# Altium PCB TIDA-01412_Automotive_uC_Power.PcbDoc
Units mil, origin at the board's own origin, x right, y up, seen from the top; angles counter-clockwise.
Board outline 2660 x 1720 mil, 2 copper layers (Top Layer, Bottom Layer), stack 40 mil thick; 78 components, 39 nets, 224 pads, 90 vias.
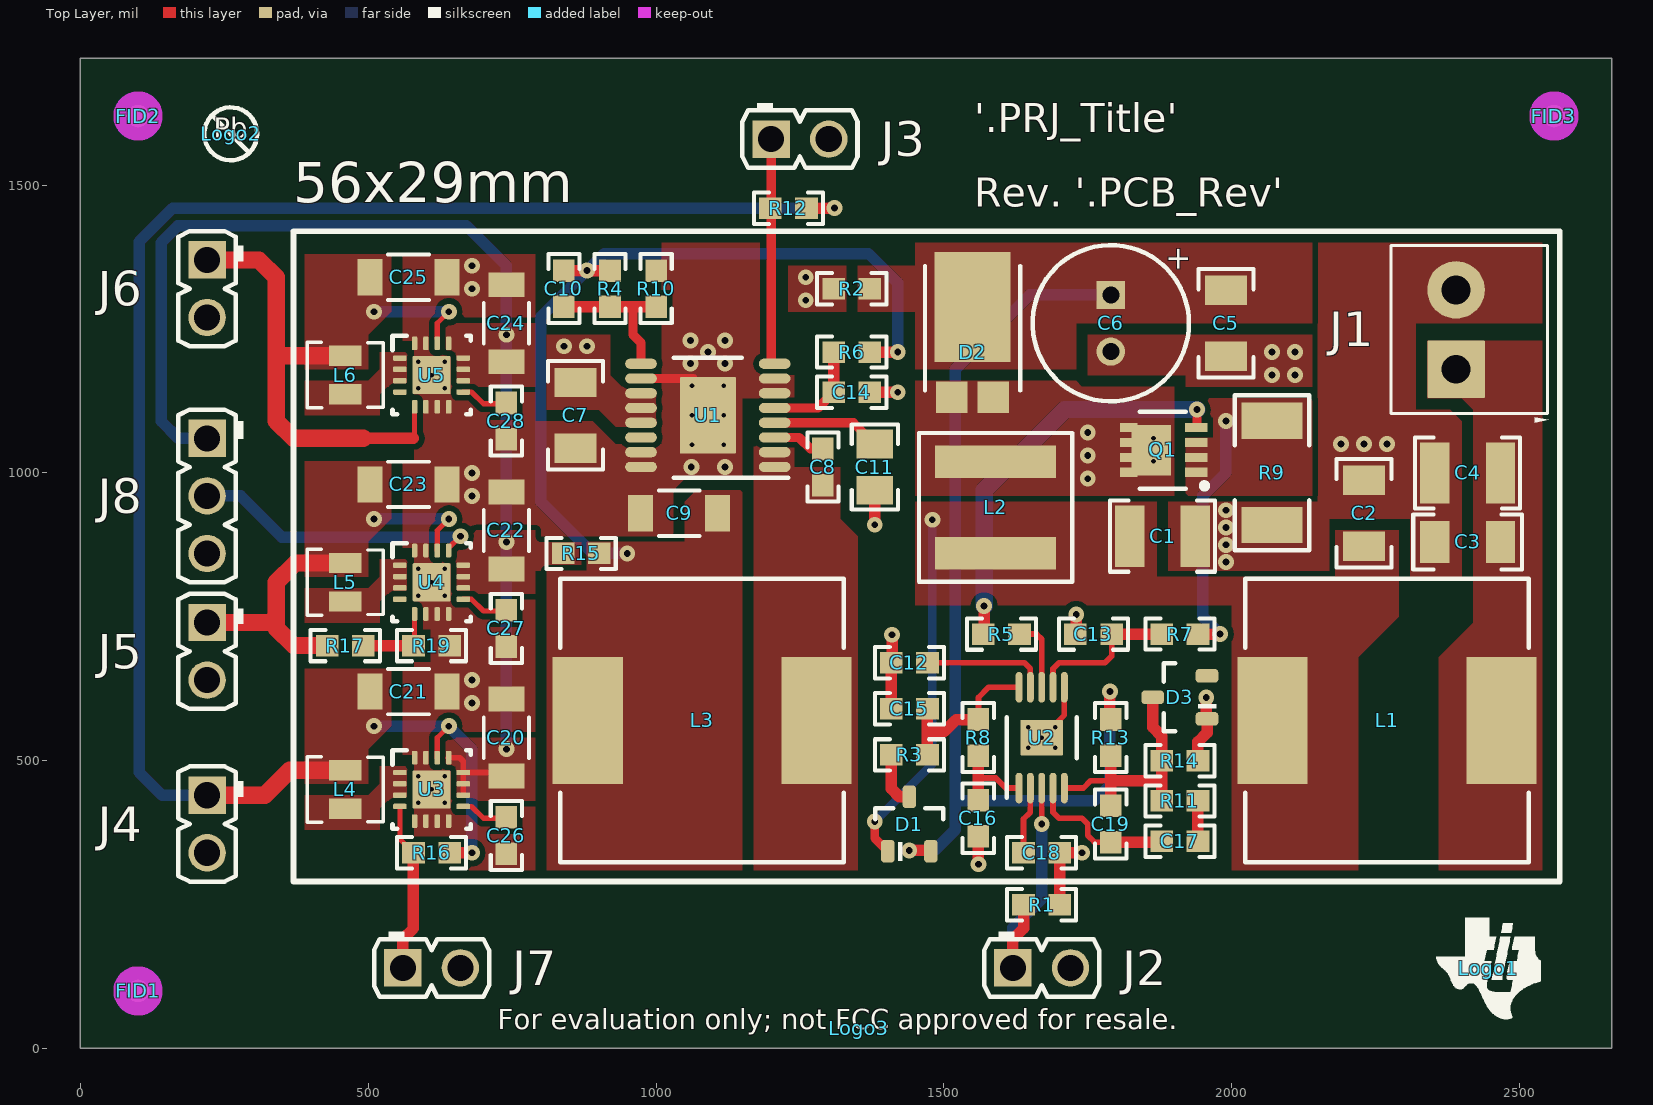
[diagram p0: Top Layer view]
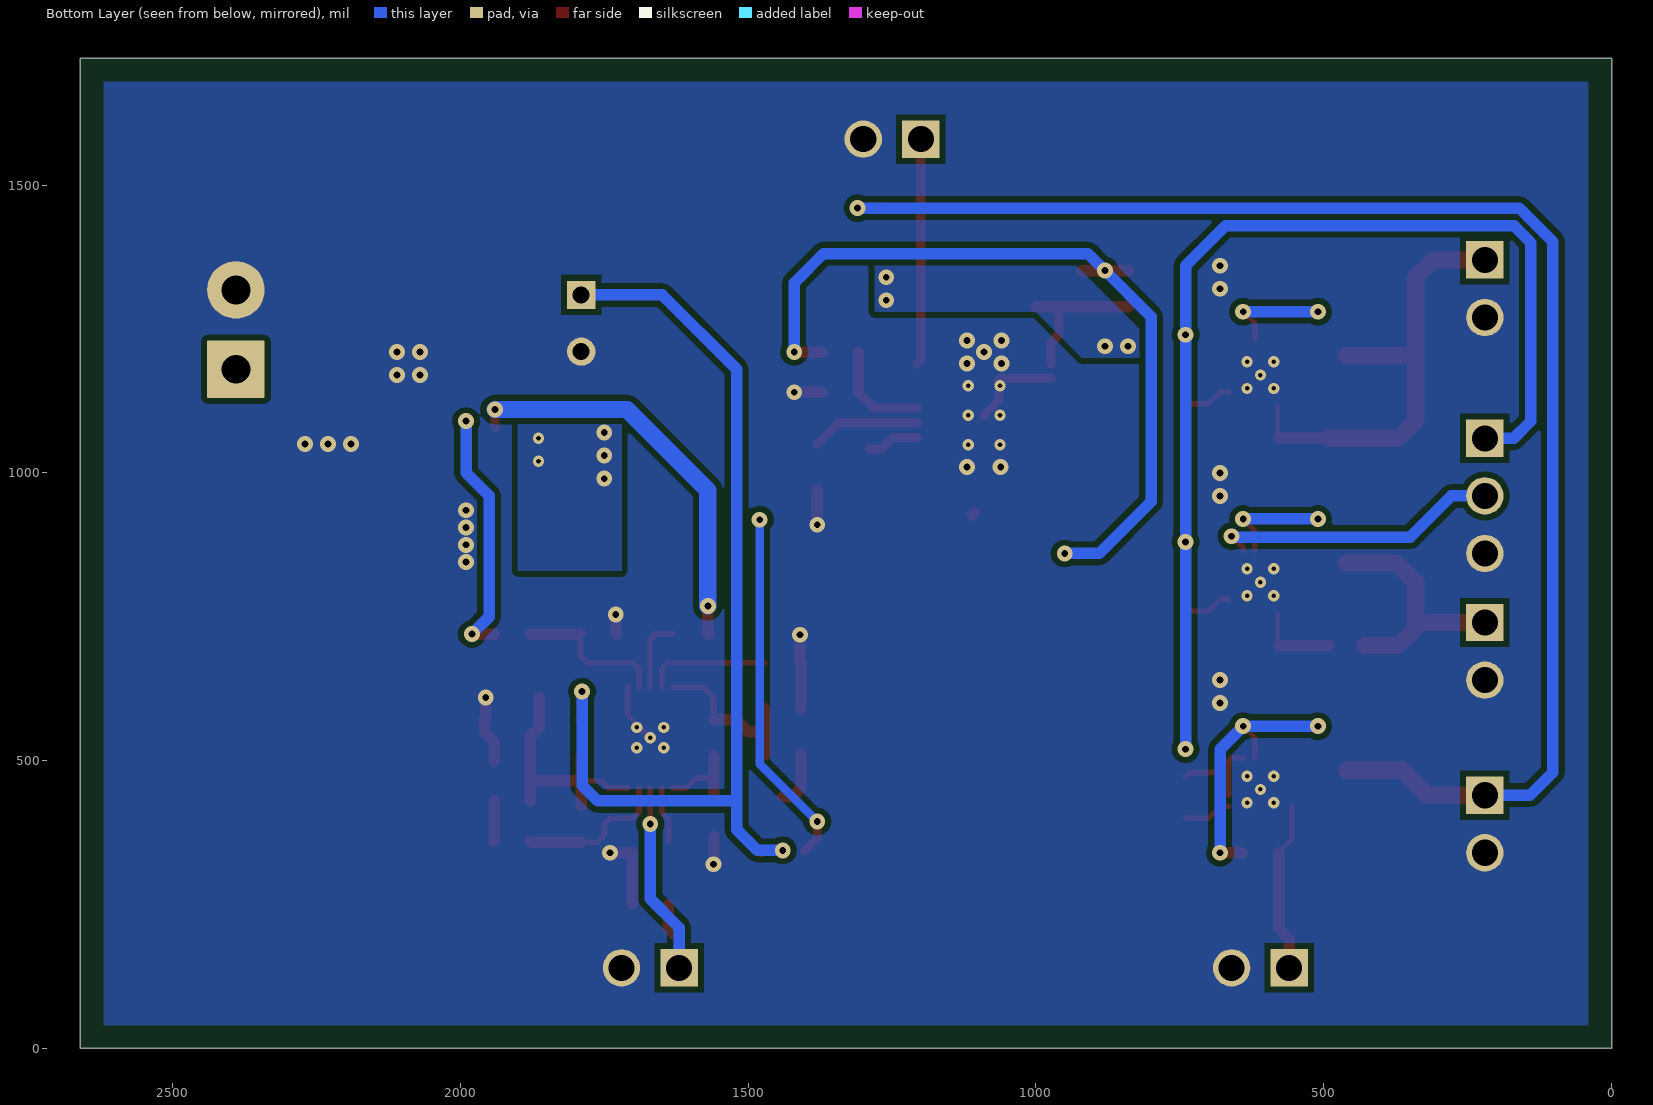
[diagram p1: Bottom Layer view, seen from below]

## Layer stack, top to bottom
Top Solder: solder mask 0.4, Solder Resist, Dk 3.5
Top Layer: signal copper 1.4
Dielectric1: core 37.2, FR-4, Dk 4.8
Bottom Layer: signal copper 1.4
Bottom Solder: solder mask 0.4, Solder Resist, Dk 3.5

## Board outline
0,0 2660,0 2660,1720 0,1720

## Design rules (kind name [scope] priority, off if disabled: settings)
AcuteAngle [All] p1: minimum=4.50000000000000E+0001 checktracksonly=FALSE
AssemblyTestPointUsage [All] p1: valid=2
BoardOutlineClearance BoardOutlineClearance_MountingHoles [OnCopper and InComponentClass('Mounting Holes')] p1: gap=40
BoardOutlineClearance BoardOutlineClearance_Poly [OnCopper and IsPoly] p2: gap=25
BoardOutlineClearance [OnCopper and Not InComponentClass('Logo') and not InComponentClass('FiducialMark') and not InRegion(1000,500,4000,800) and not InPoly] p3: gap=40
Clearance Clearance_Keepouts [((IsTrack Or IsArc) And Not InPoly) And IsFree and IsKeepOut vs ((IsTrack Or IsArc) And Not InPoly) And IsFree and IsKeepOut] p1: gap=0
Clearance Clearance_Poly [InPolygon] p2: gap=10
Clearance [All] p3: gap=7.87
ComponentClearance ComponentClearance_MountingHoles_FiducialMarks [InComponentClass('Mounting Holes') vs InComponentClass('FiducialMark')] p1: gap=50 collisioncheckmode=3 verticalgap=10 showdistances=FALSE
ComponentClearance ComponentClearance_Shunt [InComponentClass('Header') vs InComponentClass('Shunt')] p2: gap=0 collisioncheckmode=3 verticalgap=0 showdistances=FALSE
ComponentClearance ComponentClearance_Logo [InComponentClass('Logo')] p3: gap=50 collisioncheckmode=3 verticalgap=10 showdistances=FALSE
ComponentClearance ComponentClearance_ScrewToNut [(HasFootprint('NY PMS 440 0025 PH')) vs (HasFootprint('Keystone_1902C'))] p4: gap=5 collisioncheckmode=3 verticalgap=10 showdistances=FALSE
ComponentClearance ComponentClearance_MountingHoles [InComponentClass('Mounting Holes')] p5: gap=250 collisioncheckmode=3 verticalgap=100000 showdistances=FALSE
ComponentClearance ComponentClearance_SmallPassives [HasFootprint('0201*') or HasFootprint('0402*') or HasFootprint('0508') or HasFootprint('0603*') or HasFootprint('0612') or HasFootprint('0805*') or HasFootprint('0815*') or HasFootprint('0830*') or HasFootprint('1206*') or HasFootprint('1210*') or HasFootprint('1808*') or HasFootprint('1812*') or HasFootprint('1825*') or HasFootprint('2010*') or HasFootprint('2220*') or HasFootprint('2225*') or HasFootprint('2512*') or HasFootprint('2728*') or HasFootprint('3518*') vs HasFootprint('0201*') or HasFootprint('0402*') or HasFootprint('0508') or HasFootprint('0603*') or HasFootprint('0612') or HasFootprint('0805*') or HasFootprint('0815*') or HasFootprint('0830*') or HasFootprint('1206*') or HasFootprint('1210*') or HasFootprint('1808*') or HasFootprint('1812*') or HasFootprint('1825*') or HasFootprint('2010*') or HasFootprint('2220*') or HasFootprint('2225*') or HasFootprint('2512*') or HasFootprint('2728*') or HasFootprint('3518*')] p6: gap=14.96 collisioncheckmode=3 verticalgap=10 showdistances=FALSE
ComponentClearance ComponentClearance_THtoSMT [IsThruComponent vs IsSMTComponent] p7: gap=25 collisioncheckmode=3 verticalgap=30 showdistances=FALSE
ComponentClearance ComponentClearance_THtoTH [IsThruComponent vs IsThruComponent] p8: gap=20 collisioncheckmode=3 verticalgap=30 showdistances=FALSE
ComponentClearance [All] p9: gap=20 collisioncheckmode=3 verticalgap=10 showdistances=FALSE
DiffPairsRouting [All] p1: maxlimit=100 minlimit=10 mostfreqgap=10 toplayer_minwidth=15 toplayer_maxwidth=15 toplayer_prefwidth=15 bottomlayer_minwidth=15 bottomlayer_maxwidth=15 bottomlayer_prefwidth=15 maxuncoupledlength=1000
FabricationTestPointUsage TestPointUsage [All] p1: valid=2 allowmultiple=FALSE
FabricationTestpoint Testpoint [All] p1: side=3 testpointundercomponent=TRUE minsize=40 maxsize=100 preferedsize=60 minholesize=0 maxholesize=40 preferedholesize=32 testpointgrid=1 allowsidetop=TRUE allowsidebottom=TRUE usegrid=TRUE gridtolerance=0.01
FanoutControl Fanout_LCC [IsLCC] p1: bgadir=Out bgaviamode=Centered fanoutstyle=Auto fanoutdirection=Alternating viagrid=1 // Fanout_LCC (Default Rule)
FanoutControl Fanout_BGA [IsBGA] p2: bgadir=Out bgaviamode=Centered fanoutstyle=Auto fanoutdirection=Alternating viagrid=1 // Fanout_BGA (Default Rule)
FanoutControl Fanout_Default [All] p4: bgadir=Out bgaviamode=Centered fanoutstyle=Auto fanoutdirection=Alternating viagrid=1 // Fanout_Default (Default Rule)
FanoutControl Fanout_Small [(CompPinCount < 5)] p5: bgadir=Out bgaviamode=Centered fanoutstyle=Auto fanoutdirection=OutThenIn viagrid=1 // Fanout_Small (Default Rule)
HoleSize [All] p1: absolutevalues=TRUE maxlimit=251 minlimit=7.87 maxpercent=80.000 minpercent=20.000
MinimumAnnularRing MinimumAnnularRing_ThermalPadVias [IsVia and InAnyComponent] p1: minimumring=5.91
MinimumAnnularRing [All] p2: minimumring=7.87
MinimumSolderMaskSliver MinimumSolderMaskSliver_Logo [InComponentClass('Logo') vs InComponentClass('Logo')] p1: minsoldermaskwidth=0.7
MinimumSolderMaskSliver [All] p2: minsoldermaskwidth=3.94
PlaneConnect [All] p1: planeconnectstyle=Direct reliefexpansion=10 reliefentries=4 reliefconductorwidth=10 reliefairgap=10
PolygonConnect [All] p1: connectstyle=Direct reliefconductorwidth=10 reliefentries=4 polygonreliefangle="90 Angle" airgapwidth=10
RoutingVias ThermalPadVias [IsVia and InAnyComponent] p1: holewidth=7.87 width=19.68 viastyle="Through Hole" minholewidth=7.87 minwidth=19.68 maxholewidth=12.99 maxwidth=23.62
RoutingVias [All] p2: holewidth=16 width=34 viastyle="Through Hole" minholewidth=7.87 minwidth=26 maxholewidth=40 maxwidth=65
SilkToBoardRegionClearance [Not ((IsComment or IsDesignator) And (Hide <> 'False')) and not InRegion(1000,500,4000,800)] p1:
SilkToSilkClearance SilkToSilkClearance_Pb-FreeLogo [(HasFootprint('Pb-Free_Overlay_Medium') OR HasFootprint('Pb-Free_Overlay_Small')) vs (HasFootprint('Pb-Free_Overlay_Medium') OR HasFootprint('Pb-Free_Overlay_Small'))] p1: silktosilkclearance=0
SilkToSilkClearance [All] p2: silktosilkclearance=4
SilkToSolderMaskClearance [(IsPad or IsFill or IsRegion) and InComponent('D3')] p1: minsilkscreentomaskgap=3.9 clearancetoexposedcopper=TRUE
SilkToSolderMaskClearance SilkToComponentPadClearance [(IsPad or IsFill or IsRegion) and InAnycomponent] p2: minsilkscreentomaskgap=5 clearancetoexposedcopper=TRUE
SilkToSolderMaskClearance "Silk to Solder Mask Opening" [All] p3: minsilkscreentomaskgap=4 clearancetoexposedcopper=FALSE
SolderMaskExpansion [All] p1: expansion=1.97
Width [All] p1: maxlimit=100 minlimit=6 preferedwidth=10 checkconnectedcopper=TRUE
15 further rules are at their usual default settings.

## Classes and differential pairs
component class AssemblyNote: ZZ2 ZZ3 ZZ4
component class FiducialMark: FID1 FID2 FID3
component class TIDA-01412_Automotive_uC_Power_Hardware: FID1 FID2 FID3 Logo1 Logo2 Logo3 ZZ2 ZZ3 ZZ4
component class Logo: Logo1
component class Header: J2 J3 J4 J5 J6 J7 J8
component class TIDA-01412_Automotive_uC_Power: C1 C2 C3 C4 C5 C6 C7 C8 C9 C10 C11 C12 C13 C14 C15 C16 C17 C18 C19 C20 C21 C22 C23 C24 C25 C26 C27 C28 D1 D2 D3 J1 J2 J3 J4 J5 J6 J7 J8 L1 L2 L3 L4 L5 L6 Q1 R1 R2 R3 R4 R5 R6 R7 R8 R9 R10 R11 R12 R13 R14 R15 R16 R17 R19 U1 U2 U3 U4 U5

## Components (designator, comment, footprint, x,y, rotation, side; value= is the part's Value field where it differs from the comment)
C1 "GRM32ER71H475KA88L" 1210_270 1880,890 r0 top
C2 "GRM31MR71H105KA88L" 1206 2230,930 r90 top
C3 "GRM31MR71H105KA88L" 1206 2410,880 r180 top
C4 "GRM32ER71H475KA88L" 1210_270 2410,1000 r180 top
C5 "GRM31MR71H105KA88L" 1206 1990,1260 r270 top
C6 "35ZL56MEFCTA6.3X11" ZL_630x1100 1790,1260 r270 top
C7 "GRM31MR71H105KA88L" 1206 860,1100 r270 top
C8 "GRM188R71E474KA12D" 0603 1290,1010 r90 top
C9 "GCM31CR71A226KE02" 1206_180 1040,930 r180 top
C10 "GRM1885C1H101JA01D" 0603 840,1320 r270 top
C11 "GRM21BR71A475KA73L" 0805_HV 1380,1010 r90 top
C12 "GRM188R71C105KA12D" 0603 1440,670 r180 top
C13 "GRM1885C1H101JA01D" 0603 1760,720 r180 top
C14 "GCM188R71H104KA57D" 0603 1340,1140 r0 top
C15 "GCM188R71H104KA57D" 0603 1440,590 r180 top
C16 "GRM188R71H221KA01D" 0603 1560,400 r270 top
C17 "C0603X103K5RACTU" 0603 1910,360 r0 top
C18 "GCM188R71H104KA57D" 0603 1670,340 r0 top
C19 "GRM1885C1H390JA01D" 0603 1790,390 r90 top
C20 "GCM31CR71A226KE02" 1206_180 740,540 r90 top
C21 "GCM31CR71A226KE02" 1206_180 570,620 r0 top
C22 "GCM31CR71A226KE02" 1206_180 740,900 r90 top
C23 "GCM31CR71A226KE02" 1206_180 570,980 r0 top
C24 "GCM31CR71A226KE02" 1206_180 740,1260 r90 top
C25 "GCM31CR71A226KE02" 1206_180 570,1340 r0 top
C26 "GRM188R71H332KA01D" 0603 740,370 r270 top
C27 "GRM188R71H332KA01D" 0603 740,730 r270 top
C28 "GRM188R71H332KA01D" 0603 740,1090 r270 top
D1 "BAS40-05-7-F" SOT-23 1440,390 r90 top
D2 "PDS560-13" PowerDI5 1550,1210 r90 top
D3 "BZX84B8V2LT1G" SOT-23 1910,610 r180 top
FID1 "Fiducial" Fiducial10-20 100,100 r0 top
FID2 "Fiducial" Fiducial10-20 100,1620 r90 top
FID3 "Fiducial" Fiducial10-20 2560,1620 r90 top
J1 "ED555/2DS" TERM_BLK_ED555-2DS 2390,1180 r90 top
J2 "61300211121" WURTH_61300211121 1670,140 r0 top
J3 "61300211121" WURTH_61300211121 1250,1580 r0 top
J4 "61300211121" WURTH_61300211121 220,390 r270 top
J5 "61300211121" WURTH_61300211121 220,690 r270 top
J6 "61300211121" WURTH_61300211121 220,1320 r270 top
J7 "61300211121" WURTH_61300211121 610,140 r0 top
J8 "61300311121" WURTH_61300311121 220,960 r270 top
L1 "B82464–G4472–M" B82477P4 2270,570 r0 top
L2 "XAL6060-822MEB" XAL6060 1590,940 r90 top
L3 "B82464–G4222–M" B82477P4 1080,570 r180 top
L4 "VLF302510MT-2R2M" VLF302510MT 460,450 r90 top
L5 "VLF302510MT-2R2M" VLF302510MT 460,810 r90 top
L6 "VLF302510MT-2R2M" VLF302510MT 460,1170 r90 top
Logo1 "Texas Instruments" TI_Symbol_Overlay_Small 2446,139 r0 top
Logo2 "Pb-Free Symbol" Pb-Free_Overlay_Small 261,1589 r0 top
Logo3 "FCC disclaimer" FCC_disclaimer 1352,35 r0 top
Q1 "SiSA04DN-T1-GE3" PowerPAK_1212-8 1880,1040 r180 top
R1 "CRCW060310K0FKEA" 0603 1670,250 r180 top
R2 "CRCW06030000Z0EA" 0603 1340,1320 r180 top
R3 "CRCW060310R0FKEA" 0603 1440,510 r0 top
R4 "CRCW060382K5FKEA" 0603 920,1320 r90 top
R5 "CRCW06030000Z0EA" 0603 1600,720 r180 top
R6 "CRCW06033R01FKEA" 0603 1340,1210 r0 top
R7 "CRCW06031K00FKEA" 0603 1910,720 r0 top
R8 "CRCW0603221KFKEA" 0603 1560,540 r90 top
R9 "WSL2010R0200FEA18" 2010 2070,1000 r90 top
R10 "CRCW060316K5FKEA" 0603 1000,1320 r270 top
R11 "CRCW060333K2FKEA" 0603 1910,430 r0 top
R12 "CRCW060310K0FKEA" 0603 1230,1460 r0 top
R13 "CRCW0603200KFKEA" 0603 1790,540 r90 top
R14 "CRCW060316K9FKEA" 0603 1910,500 r180 top
R15 "CRCW06030000Z0EA" 0603 870,860 r0 top
R16 "CRCW060310K0FKEA" 0603 610,340 r0 top
R17 "CRCW060373K2FKEA" 0603 460,700 r180 top
R19 "CRCW060323K2FKEA" 0603 610,700 r180 top
U1 "LM53603AQPWPRQ1" PWP0016H_N 1090,1100 r180 top
U2 "TPS40210QDGQRQ1" DGQ0010D_N 1670,540 r90 top
U3 "TPS62133AQRGTRQ1" RGT0016C 610,450 r0 top
U4 "TPS62130AQRGTRQ1" RGT0016C 610,810 r0 top
U5 "TPS6213013AQRGTRQ1" RGT0016C 610,1170 r0 top
ZZ2 "These assemblies are ESD sensitive, ESD precautions shall be observed." AssemblyNote 13,2036.11 r0 top
ZZ3 "These assemblies must be clean and free from flux and all contaminants. Use of no clean flux is not acceptable." AssemblyNote 13,1947.56 r0 top
ZZ4 "These assemblies must comply with workmanship standards IPC-A-610 Class 2, unless otherwise specified." AssemblyNote 13,1859 r0 top

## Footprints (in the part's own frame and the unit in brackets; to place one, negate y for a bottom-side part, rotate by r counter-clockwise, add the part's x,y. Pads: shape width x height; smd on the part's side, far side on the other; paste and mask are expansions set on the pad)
0603 [mm] "0603 from SM-752 data"
  rect 1x0.95 smd: 1(-0.8,0) 2(0.8,0)
  silkscreen extent -1.52,-0.69 1.52,0.69, body extent -0.87,-0.47 0.87,0.47, height 1
0805_HV [mil] "0805 with 30mil clearance between pads"
  rect 50x63 smd: 1(-40,0) 2(40,0)
  silkscreen extent -74,-40 74,40, body extent -43,-29 43,29, height 57
1206 [mm] "1206 from SM-752 data"
  rect 1.3x1.85 smd: 1(-1.45,0) 2(1.45,0)
  silkscreen extent -2.4,-1.21 2.4,1.21, body extent -1.7,-0.9 1.7,0.9, height 1.35
1206_180 [mm] "1206_180"
  rect 1.1x1.6 smd: 1(-1.7,0) 2(1.7,0)
  silkscreen extent -0.9,-1 0.9,1, body extent -1.75,-0.95 1.75,0.95, height 1.8
1210_270 [mm] "1210"
  rect 1.3x2.7 smd: 1(-1.45,0) 2(1.45,0)
  silkscreen extent -2.32,-1.57 2.32,1.57, body extent -1.7,-1.35 1.7,1.35, height 2.7
2010 [mm] "Chip Capacitor, Body 5.08x2.54mm, IPC Medium Density"
  rect 1.6x2.7 smd: 1(-2.3,0) 2(2.3,0)
  silkscreen extent -3.42,-1.65 3.42,1.65, body extent -2.73,-1.45 2.73,1.45, height 1.66
AssemblyNote [mil] "Assembly Note"
B82477P4 [mm] "SMD, 2-Leads, Body 12.5x12.5mm"
  rect 3.1x5.6 smd: 1(-5.05,0) 2(5.05,0)
  silkscreen extent -6.25,-6.25 6.25,6.25, body extent -6.25,-6.25 6.25,6.25, height 8.5
DGQ0010D_N [mm] "TSSOP, 10-Leads, Body 3x3mm, Pitch 0.5mm, Thermal Pad 1.88x1.57mm, IPC Medium Density"
  rrect100% 1.35x0.3 smd: 1(-2.225,1) 2(-2.225,0.5) 3(-2.225,0) 4(-2.225,-0.5) 5(-2.225,-1) 6(2.225,-1) 7(2.225,-0.5) 8(2.225,0) 9(2.225,0.5) 10(2.225,1)
  rrect6% 1.57x1.88 smd: 11(0,0)
  silkscreen extent -2.65,-1.55 0.9,1.55, body extent -2.46,-1.5 2.46,1.5, height 1.1
FCC_disclaimer [mil]
Fiducial10-20 [mm]
  round 1 smd mask+0.5: 1(0,0)
  Top Layer keep-out circle w1.178: c0,0 r0.5
Pb-Free_Overlay_Small [mil]
  silkscreen extent -46,-46 46,46
PowerDI5 [mm] "Diodes Inc recommended land pattern, ap02001.pdf rev 60"
  rect 1.4x1.39 smd: 1(-1.991,0.92) 2(-1.991,-0.92)
  rect 4.86x3.36 smd: 3(1.991,0)
  silkscreen extent -1.7,-2.1 3.8,2.1, body extent -2.27,-2.03 4.33,2.03, height 1.17
PowerPAK_1212-8 [mil] "Vishay PowerPAK 1212-8, Body 3.4x3.2mm (max), Pitch 0.65mm, IPC Medium Density"
  rect 39x16 smd mask+2.01: 1(-58.75,39) 2(-58.75,13) 3(-58.75,-13) 4(-58.75,-39)
  rect 30x16 smd mask+2.01: 5(58.75,-39) 6(58.75,-13) 7(58.75,13) 8(58.75,39)
  rect 68x88 smd mask+2.01: 9(19.75,0.61)
  silkscreen extent -78,-66 40,68, body extent -65,-65 65,65, height 43
PWP0016H_N [mm] "TSOP, 16-Leads, Body 5x4.4mm, Pitch 0.65mm, Thermal Pad 2.48x3.37 mm, IPC Medium Density"
  rrect100% 1.4x0.45 smd: 1(-2.95,2.275) 2(-2.95,1.625) 3(-2.95,0.975) 4(-2.95,0.325) 5(-2.95,-0.325) 6(-2.95,-0.975) 7(-2.95,-1.625) 8(-2.95,-2.275) 9(2.95,-2.275) 10(2.95,-1.625) 11(2.95,-0.975) 12(2.95,-0.325) 13(2.95,0.325) 14(2.95,0.975) 15(2.95,1.625) 16(2.95,2.275)
  rrect4% 2.48x3.37 smd: 17(0,0)
  silkscreen extent -3.55,-2.55 1.5,2.75, body extent -3.21,-2.5 3.21,2.5, height 1
RGT0016C [mm] "QFN, 16-Leads, Body 3x3mm, Pitch 0.5mm, Thermal Pad 1.7x1.7mm, TI Recommended"
  rrect42% 0.6x0.24 smd: 1(-1.4,0.75) 2(-1.4,0.25) 3(-1.4,-0.25) 4(-1.4,-0.75) 9(1.4,-0.75) 10(1.4,-0.25) 11(1.4,0.25) 12(1.4,0.75)
  rrect42% 0.24x0.6 smd: 5(-0.75,-1.4) 6(-0.25,-1.4) 7(0.25,-1.4) 8(0.75,-1.4) 13(0.75,1.4) 14(0.25,1.4) 15(-0.25,1.4) 16(-0.75,1.4)
  rrect6% 1.55x1.55 on Top Paste: 17(0,0)
  rrect6% 1.68x1.68 smd paste-0.85: 17(0,0)
  silkscreen extent -1.72,-1.73 1.72,1.73, body extent -1.5,-1.5 1.5,1.5, height 1
SOT-23 [mm] "SOT23, 3-Leads, Body 2.9x1.3mm, Pitch 0.95mm, Lead Span 2.5mm, IPC Medium Density"
  rrect50% 1x0.6 smd: 1(-1.2,0.95) 2(-1.2,-0.95) 3(1.2,0)
  silkscreen extent -1.63,-1.5 0.7,1.5, body extent -1.16,-1.45 1.21,1.45, height 1
TERM_BLK_ED555-2DS [mil]
  rrect4% 100x100 hole 50: 1(0,0)
  round 100 hole 50: 2(138,0)
  silkscreen extent -93,-161 215,113, body extent -69,-150 207,106, height 323
TI_Symbol_Overlay_Small [mil]
  silkscreen extent -90,-88 91,88
VLF302510MT [mm] "TDK"
  rect 0.9x1.45 smd: 1(-0.85,0) 2(0.85,0)
  silkscreen extent -1.45,-1.68 1.45,1.68, body extent -1.35,-1.6 1.35,1.6, height 1
WURTH_61300211121 [mm] "Header, 2.54mm, 2x1, TH"
  rect 1.65x1.65 hole 1.15: 1(-1.27,0)
  round 1.65 hole 1.15: 2(1.27,0)
  silkscreen extent -2.54,-1.27 2.54,1.6, body extent -2.54,-1.27 2.54,1.27, height 8.54
WURTH_61300311121 [mm] "Header, 2.54mm, 3x1, TH"
  rect 1.65x1.65 hole 1.15: 1(-2.54,0)
  round 1.65 hole 1.15: 2(0,0) 3(2.54,0)
  silkscreen extent -3.81,-1.27 3.81,1.6, body extent -3.81,-1.27 3.81,1.27, height 8.54
XAL6060 [mil] "Coilcraft recommended land pattern Document 887-4 Revised 11/20/12"
  rect 56x210 smd: 1(-79.5,0) 2(79.5,0)
  silkscreen extent -129,-133 129,133, body extent -129,-133 129,133, height 240
ZL_630x1100 [mm] "RUBYCON"
  rect 1.25x1.25 hole 0.75: 1(-1.25,0)
  round 1.25 hole 0.75: 2(1.25,0)
  silkscreen extent -3.45,-3.45 3.45,3.45, body extent -3.37,-3.39 3.4,3.39, height 12.51

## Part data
C1 C4: "CAP, CERM, 4.7 µF, 50 V, +/- 10%, X7R, 1210"
C2 C3 C5 C7: "CAP, CERM, 1 µF, 50 V, +/- 10%, X7R, 1206"
C6: "CAP, AL, 56 µF, 35 V, +/- 20%, 0.13 ohm, TH"
C8: "CAP, CERM, 0.47 µF, 25 V, +/- 10%, X7R, 0603"
C9 C20 C21 C22 C23 C24 C25: "CAP, CERM, 22 µF, 10 V, +/- 10%, X7R, AEC-Q200 Grade 1, 1206"
C10 C13: "CAP, CERM, 100 pF, 50 V, +/- 5%, C0G/NP0, 0603"
C11: "CAP, CERM, 4.7 µF, 10 V, +/- 10%, X7R, 0805"
C12: "CAP, CERM, 1 µF, 16 V, +/- 10%, X7R, 0603"
C14 C15 C18: "CAP, CERM, 0.1 µF, 50 V, +/- 10%, X7R, 0603"
C16: "CAP, CERM, 220 pF, 50 V, +/- 10%, X7R, 0603"
C17: "CAP, CERM, 0.01 µF, 50 V, +/- 10%, X7R, 0603"
C19: "CAP, CERM, 39 pF, 50 V, +/- 5%, C0G/NP0, 0603"
C26 C27 C28: "CAP, CERM, 3300 pF, 50 V, +/- 10%, X7R, 0603"
D1: "Diode, Schottky, 40 V, 0.2 A, SOT-23"
D2: "Diode, Schottky, 60 V, 5 A, PowerDI5"
D3: "Diode, Zener, 8.2 V, 225 mW, SOT-23"
FID1 FID2 FID3: "Fiducial mark.  There is nothing to buy or mount."
J1: "Terminal Block, 6A, 3.5mm Pitch, 2-Pos, TH"
J2 J3 J4 J5 J6 J7: "Header, 2.54 mm, 2x1, Gold, TH"
J8: "Header, 2.54 mm, 3x1, Gold, TH"
L1: library part B82477P4103M000, "Inductor, Shielded, Ferrite, 4.7 µH, 4.9 A, 0.015 ohm, SMD"
L2: "Inductor, Shielded, Composite, 8.2 µH, 8.4 A, 0.02 ohm, SMD"
L3: library part B82477P4103M000, "Inductor, Shielded, Ferrite, 2.2 µH, 6.5 A, 0.01 ohm, SMD"
L4 L5 L6: "Inductor, Shielded, Ferrite, 2.2 µH, 1.23 A, 0.084 ohm, SMD"
Logo1: library part TI_Logo, "Texas Instrument Corporate Signature"
Logo2: library part Pb-Free
Logo3: library part FCC_disclaimer, "FCC_disclaimer"
Q1: "MOSFET, N-CH, 30 V, 40 A, PowerPAK 1212"
R1 R12 R16: "RES, 10.0 k, 1%, 0.1 W, 0603"
R2 R5 R15: "RES, 0, 5%, 0.1 W, 0603"
R3: "RES, 10.0, 1%, 0.1 W, 0603"
R4: "RES, 82.5 k, 1%, 0.1 W, 0603"
R6: "RES, 3.01, 1%, 0.1 W, 0603"
R7: "RES, 1.00 k, 1%, 0.1 W, 0603"
R8: "RES, 221 k, 1%, 0.1 W, 0603"
R9: "RES, 0.02, 1%, 1 W, 2010"
R10: "RES, 16.5 k, 1%, 0.1 W, 0603"
R11: "RES, 33.2 k, 1%, 0.1 W, 0603"
R13: "RES, 200 k, 1%, 0.1 W, 0603"
R14: "RES, 16.9 k, 1%, 0.1 W, 0603"
R17: "RES, 73.2 k, 1%, 0.1 W, 0603"
R19: "RES, 23.2 k, 1%, 0.1 W, 0603"
U1: "5V/3.3V/ADJ, 3A, Buck Regulator For Automotive Applications, PWP0016H"
U2: "4.5-V TO 52-V INPUT CURRENT MODE BOOST CONTROLLER, DGQ0010D"
U3 U4: "3V to 17-V 3A Step-Down Converter with DCS-Control™, RGT0016C"
U5: "3V-17V 3A Step-Down Converter With DCS-Control, RGT0016C (VQFN-16)"
ZZ2 ZZ3 ZZ4: library part AssemblyNote

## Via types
v1: diameter 27.56, hole 11.81, Top Layer to Bottom Layer, tented both sides, 62 vias
v2: diameter 19.68, hole 7.87, Top Layer to Bottom Layer, 22 vias
v3: diameter 19.68, hole 7.87, Top Layer to Bottom Layer, tented top, 6 vias

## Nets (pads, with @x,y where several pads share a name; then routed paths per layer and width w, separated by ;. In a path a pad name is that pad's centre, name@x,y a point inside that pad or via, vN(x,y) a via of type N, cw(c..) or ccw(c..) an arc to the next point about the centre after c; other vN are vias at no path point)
GND: C1.2 C2.2 C3.2 C4.2 C5.2 C6.2 C7.2 C9.2 C11.1 C12.2 C13.2 C14.2 C15.2 C16.2 C18.2 C20.2 C21.2 C22.2 C23.2 C24.2 C25.2 C26.2 C27.2 C28.2 D3.1 J1.2 J2.2 J3.2 J4.2 J5.2 J6.2 J7.2 J8.3 R1.1 R9.1 R10.1 R14.1 R19.1 U1.6 U1.7 U1.10 U1.15 U1.16 U1.17 U2.6 U2.11 U3.5 U3.6 U3.7 U3.8 U3.15 U3.16 U3.17@610,450 U4.6 U4.7 U4.8 U4.15 U4.16 U4.17@610,810 U5.6 U5.7 U5.8 U5.15 U5.16 U5.17@610,1170 | length 835.4
  Top Layer w10: v2(1670,540) 1709.37,579.37 U2.6
  Top Layer w16: U1.10 1063.98,1163.98 1063.98,1126.02 U1.17
  Top Layer w20: C14.2 v1(1420,1140) ; v1(1380,910) C11.1 ; C15.2 C12.2 1410,671.5 v1(1410,718.7) ; v1(1560,320) C16.2 ; R1.1 C18.2 v1(1740,340) ; C13.2 1730,721.5 v1(1730,754.02) ; R14.1 1941.5,532.6 1957.24,548.35 D3.1 1955.79,574.06 v1(1955.79,610)
  other v1: 680,600 680,640 1990,845 1990,875 1990,905 1990,935 680,960 680,1000 1061.3,1010 1120,1010 2190,1050 2230,1050 2270,1050 2070,1170 2110,1170 1060,1190 1120,1190 1090,1210 2070,1210 2110,1210 1060,1230 1120,1230 680,1320 680,1360
  other v2: 586.77,426.77 633.23,426.77 610,450 586.77,473.23 633.23,473.23 1646.38,522.28 1693.62,522.28 1646.38,557.72 1693.62,557.72 586.77,786.77 633.23,786.77 610,810 586.77,833.23 633.23,833.23 586.77,1146.77 633.23,1146.77 610,1170 586.77,1193.23 633.23,1193.23
  other v3: 1062.44,1048.82 1117.56,1048.82 1062.44,1100 1117.56,1100 1062.44,1151.18 1117.56,1151.18
NetC1_1: C1.1 C2.1 D1.1 L1.1 L2.1 | length 626.7
  Top Layer w15: v1(1380,394.21) 1380,365.35 D1.1
  Bottom Layer w15: v1(1380,394.21) 1480,494.21 v1(1480,918.7)
NetC3_1: C3.1 C4.1 J1.1 L1.2
NetC7_1: C7.1 R2.2 U1.11 U1.12 U1.13
  other v1: 840,1220 880,1220 1260,1300 1260,1340
NetC8_1: C8.1 L3.1 U1.1 U1.2
NetC8_2: C8.2 U1.3 | length 92.2
  Top Layer w16: U1.3 1248.39,1061.61 1268.5,1041.5 C8.2
NetC9_1: C9.1 C10.1 L3.2 R4.2 R6.2 R15.2 | length 1448.1
  Top Layer w20: C10.1 v1(880,1351.5) R4.2 ; C9.1 C9.1@1110,926.93 ; R6.2 v1(1420,1210)
  Bottom Layer w20: v1(950,860) 890,860 800,950 800,1271.5 v1(880,1351.5) 880.47,1351.5 910,1381.02 1368.98,1381.02 1420,1330 v1(1420,1210)
NetC10_2: C10.2 R4.1 R10.2 U1.9 | length 264.7
  Top Layer w16: 960,1288.5 960,1240 973.86,1226.14 U1.9
  Top Layer w20: C10.2 R4.1 960,1288.5 R10.2
NetC11_2: C11.2 U1.4 | length 189.3
  Top Layer w16: U1.4 1342.8,1087.2 C11.2
NetC12_1: C12.1 U2.9 | length 215.2
  Top Layer w10: C12.1 1640,670 1650.31,659.69 U2.9
NetC13_1: C13.1 R7.1 U2.7 | length 268.4
  Top Layer w10: U2.7 1689.68,659.68 1700,670 1780,670 1791.5,681.5 C13.1
  Top Layer w20: C13.1 R7.1
NetC14_1: C14.1 R6.1 U1.5 | length 183.6
  Top Layer w16: U1.5 1281.3,1112.8 C14.1
  Top Layer w20: C14.1 R6.1
NetC15_1: C15.1 R3.2 R8.2 U2.10 | length 293.8
  Top Layer w10: R8.2 1560,610 1577.6,627.6 U2.10
  Top Layer w20: R3.2 1471.5,550 ; C15.1 1471.5,550 ; R8.2 1521.5,571.5 1500,550 1471.5,550
NetC16_1: C16.1 R8.1 U2.1 | length 154.9
  Top Layer w10: 1560,470 1590,470 1607.6,452.4 U2.1
  Top Layer w20: C16.1 1560,470 R8.1
NetC17_1: C17.1 C19.1 U2.4 | length 264.7
  Top Layer w10: U2.4 1689.68,410.32 1700,400 1740,400 1750,390 1750,370 1761.5,358.5 C19.1
  Top Layer w20: C19.1 1877.01,358.5 C17.1
NetC17_2: C17.2 R11.2 | length 70
  Top Layer w20: C17.2 R11.2
NetC18_1: C18.1 U2.2 | length 97.3
  Top Layer w10: 1638.5,360 1638.5,398.5 1650.31,410.31 U2.2
NetC19_2: C19.2 D3.3 R11.1 R13.1 R14.2 U2.5 | length 450
  Top Layer w10: U2.5 1742.4,452.4 1755,465 1790,465
  Top Layer w20: C19.2 1790,465 ; R13.1 1790,465 ; D3.3 1862.76,558.35 1878.5,542.6 R14.2 1878.5,470 ; R11.1 1878.5,470 ; 1790,465 1873.5,465 1878.5,470
NetC20_1: C20.1 C22.1 C24.1 J8.1 R15.1 U3.10 U3.11 U3.12 U3.13 U4.10 U4.11 U4.12 U5.10 U5.11 U5.12 U5.13 | length 2047.8
  Top Layer w10: U3.13 658.88,505.12 665.12,498.88 U3.12 ; U3.10 U3.11 U3.12 ; C20.1 733.54,479.53 U3.12
  Bottom Layer w20: J8.1 170,1060 140,1090 140,1400 169.4,1429.4 670.6,1429.4 740,1360 v1(740,1240) v1(740,520)
  other v1: 740,880
NetC23_1: C23.1 J5.1 L5.2 R17.2 U4.14 | length 632.2
  Top Layer w9: U4.14 619.84,899.84 v1(640,920)
  Top Layer w30: J5.1 330,740 340,750 ; R17.2 370,700 340,730 340,750 ; L5.2 373.46,843.46 340,810 340,750
  Bottom Layer w20: v1(510,920) v1(640,920)
NetC25_1: C25.1 J6.1 L6.2 U5.5 U5.14 | length 996.4
  Top Layer w9: 578.5,1060 580.47,1061.97 U5.5 ; U5.14@619.84,1233.66 619.84,1259.84 v1(640,1280)
  Top Layer w20: 491.5,1060 578.5,1060
  Top Layer w30: J6.1 310,1370 340,1340 340,1210 ; L6.2 346.54,1203.46 340,1210 ; 491.5,1060 370,1060 340,1090 340,1210
  Bottom Layer w20: v1(510,1280) v1(640,1280)
NetC26_1: C26.1 U3.9 | length 84
  Top Layer w9: U3.9 679.53,420.47 700,400 738.5,400 C26.1
NetC27_1: C27.1 U4.9 | length 84
  Top Layer w9: U4.9 679.53,780.47 700,760 738.5,760 C27.1
NetC28_1: C28.1 U5.9 | length 84
  Top Layer w9: U5.9 679.53,1140.47 700,1120 738.5,1120 C28.1
NetD1_3: D1.3 R3.1 | length 95.9
  Top Layer w20: R3.1 1408.5,451.5 1422.76,437.24 D1.3
NetD2_1: D2.1 D2.2 L2.2 Q1.5 Q1.6 Q1.7 Q1.8 Q1.9
  other v1: 1750,990 1750,1030 1750,1070
  other v2: 1864.25,1020 1864.25,1060
NetJ2_1: J2.1 R1.2 U2.3 | length 450.8
  Top Layer w10: v1(1670,390) U2.3
  Top Layer w20: J2.1 1620,190 1638.5,208.5 R1.2
  Bottom Layer w20: J2.1 1620,210 1670,260 v1(1670,390)
NetJ3_1: J3.1 R12.1 U1.8 | length 393
  Top Layer w16: J3.1 1200,1195.71 U1.8
NetJ7_1: J7.1 R16.1 U3.4 | length 297.9
  Top Layer w9: U3.4 554.88,363.62 R16.1
  Top Layer w20: J7.1 560,190 578.5,208.5 R16.1
NetJ8_2: J8.2 U4.13 | length 503.7
  Top Layer w9: U4.13 639.53,869.53 v1(660,890)
  Bottom Layer w20: J8.2 278.35,960 350,888.35 658.35,888.35 v1(660,890)
NetL4_1: L4.1 U3.1 U3.2 U3.3
NetL5_1: L5.1 U4.1 U4.2 U4.3
NetL6_1: L6.1 U5.1 U5.2 U5.3
NetQ1_1: Q1.1 Q1.2 Q1.3 R7.2 R9.2 | length 437.5
  Top Layer w20: R7.2 v1(1980,720)
  Bottom Layer w20: v1(1980,720) 1950,750 1950,960 1990,1000 v1(1990,1090)
NetQ1_4: Q1.4 R5.2 | length 710.1
  Top Layer w16: Q1.4 1940,1080.25 v1(1940,1110)
  Top Layer w20: R5.2 1570,721.5 v1(1570,768.7)
  Bottom Layer w30: v1(1570,768.7) 1570,970 1710,1110 v1(1940,1110)
NetR5_1: R5.1 U2.8 | length 125.6
  Top Layer w10: R5.1 1661.02,720 1670,711.02 U2.8
NetR17_1: R17.1 R19.2 U4.5 | length 142.7
  Top Layer w9: R19.2 580.47,701.97 U4.5
  Top Layer w20: R17.1 R19.2
P5V0: C21.1 J4.1 L4.2 R12.2 R16.2 U3.14 | length 3063.7
  Top Layer w9: U3.14 619.84,539.84 v1(640,560)
  Top Layer w20: R16.2 v1(680,340) ; R12.2 v1(1310,1460)
  Top Layer w30: J4.1 320,440 363.46,483.46 L4.2
  Bottom Layer w20: J4.1 141.78,440 101.78,480 101.78,1401.78 160,1460 v1(1310,1460) ; v1(510,560) v1(640,560) 680,520 v1(680,340)
VBOOST: C5.1 C6.1 D1.2 D2.3 R2.1 R13.2 | length 1748.1
  Top Layer w20: v1(1440,344.21) 1475.94,344.21 D1.2 ; v1(1788.54,620) 1788.54,572.95 R13.2
  Bottom Layer w20: v1(1440,344.21) 1484.21,344.21 1520,380 1520,430 ; v1(1788.54,620) 1788.54,457.09 1761.46,430 1520,430 ; C6.1 1649.21,1309.21 1520,1180 1520,430
pads on no net: D3.2 FID1.1 FID2.1 FID3.1 U1.14 U3.17@610,450 U4.4 U4.17@610,810 U5.4 U5.17@610,1170

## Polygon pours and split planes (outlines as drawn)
NetC25_1 on Top Layer "Top Layer-No Net" (solid, remove dead copper, pour order 62): 500,1180 500,1240 540,1280 540,1380 390,1380 390,1180
NetL6_1 on Top Layer "Top Layer-No Net 1" (solid, remove dead copper, pour order 64): 390,1160 500,1160 520,1180 520,1210 570,1210 570,1150 532.99,1150 520,1137.01 520,1100 390,1100
NetC20_1 on Top Layer "Top Layer-No Net 2" (solid, remove dead copper, pour order 66): 790,1150 651.56,1150 651.56,1210 630,1210 630,1260 790,1260
GND on Top Layer "Top Layer-No Net 3" (solid, remove dead copper, pour order 68): 790,1380 560,1380 560,1230 580,1230 580,1010 790,1010 790,1280
NetC20_1 on Top Layer "Top Layer-No Net 2" (solid, remove dead copper, pour order 70): 790,790 651.56,790 651.56,850 630,850 630,900 790,900
GND on Top Layer "Top Layer-No Net 3" (solid, remove dead copper, pour order 72): 790,1020 560,1020 560,870 580,870 580,650 790,650 790,920
NetC23_1 on Top Layer "Top Layer-No Net" (solid, remove dead copper, pour order 74): 500,820 500,880 540,920 540,1020 390,1020 390,820
NetL5_1 on Top Layer "Top Layer-No Net 1" (solid, remove dead copper, pour order 76): 390,800 500,800 520,820 520,850 570,850 570,790 532.99,790 520,777.01 520,740 390,740
GND on Top Layer "Top Layer-No Net 3" (solid, remove dead copper, pour order 80): 790,660 560,660 560,510 580,510 580,310 790,310 790,560
NetC20_1 on Top Layer "Top Layer-No Net 2" (solid, remove dead copper, pour order 78): 790,430 651.56,430 651.56,490 630,490 630,540 790,540
P5V0 on Top Layer "Top Layer-No Net" (solid, remove dead copper, pour order 82): 500,460 500,520 540,560 540,660 390,660 390,460
NetL4_1 on Top Layer "Top Layer-No Net 1" (solid, remove dead copper, pour order 84): 390,440 500,440 520,460 520,490 570,490 570,430 532.99,430 520,417.01 520,380 390,380
NetC8_1 on Top Layer "Top Layer-No Net 4" (solid, remove dead copper, pour order 86): 1240,1050 1170,1050 1170,310 1350,310 1350,890 1320,920 1320,1010 1240,1010
NetC9_1 on Top Layer "Top Layer-No Net 5" (solid, remove dead copper, pour order 88): 1150,970 1150,310 810,310 810,830 880,830 880,880 920,880 950,880 1030,880 1040,880 1050,880 1050,910 1050,950 1070,970 1110,970
GND on Top Layer "Top Layer-No Net 6" (solid, remove dead copper, pour order 90): 1030,890 1030,970 1050,990 1150,990 1150,1130 1240,1130 1240,1170 1180,1170 1180,1400 1010,1400 1010,1050 930,1050 890,1090 780,1090 780,890
NetC7_1 on Top Layer "Top Layer-No Net 7" (solid, remove dead copper, pour order 92): 810,1110 900,1110 930,1080 1010,1080 1010,1150 940,1150 920,1170 920,1240 810,1240
NetC20_1 on Top Layer "Top Layer-No Net 8" (solid, remove dead copper, pour order 94): 870,890 870,830 700,830 700,890
NetC1_1 on Top Layer "Top Layer-No Net 9" (solid, remove dead copper, pour order 96): 1870,770 1870,950 1450,950 1450,770
VBOOST on Top Layer "Top Layer-No Net 11" (solid, remove dead copper, pour order 98): 1450,1400 1450,1180 1660,1180 1730,1180 1730,1260 2140,1260 2140,1400
NetQ1_1 on Top Layer "Top Layer-No Net 12" (solid, remove dead copper, pour order 100): 1920,960 2140,960 2140,1130 1920,1130
GND on Top Layer "Top Layer-No Net 13" (solid, remove dead copper, pour order 102): 2140,1150 1920,1150 1920,1170 1750,1170 1750,1240 2140,1240
NetD2_1 on Top Layer "Top Layer-No Net 10" (solid, remove dead copper, pour order 104): 1450,1160 1450,960 1900,960 1900,1150 1740,1150 1730,1160
GND on Top Layer "Top Layer-No Net 14" (solid, remove dead copper, pour order 106): 1890,950 2170,950 2170,830 1890,830
VBOOST on Top Layer "Top Layer-No Net 15" (solid, remove dead copper, pour order 108): 1350,1360 1460,1360 1460,1280 1350,1280
NetC7_1 on Top Layer "Top Layer-No Net 16" (solid, remove dead copper, pour order 110): 1330,1280 1330,1360 1230,1360 1230,1280
NetC1_1 on Top Layer "Top Layer-No Net 17" (solid, remove dead copper, pour order 112): 1850,820 2180,820 2180,900 2290,900 2290,750 2220,680 2220,310 2000,310 2000,770 1850,770
NetC3_1 on Top Layer "Top Layer-No Net 18" (solid, remove dead copper, pour order 114): 2360,310 2540,310 2540,1230 2340,1230 2340,1130 2400,1130 2420,1110 2420,740 2360,680
GND on Top Layer "Top Layer-No Net 19" (solid, remove dead copper, pour order 116): 2540,1260 2320,1260 2320,1110 2380,1110 2400,1090 2400,820 2310,820 2310,920 2150,920 2150,1400 2540,1400
NetD2_1 on Bottom Layer "Bottom Layer-No Net 3" (solid, remove dead copper, pour order 118): 1900,1090 1720,1090 1720,830 1900,830
GND on Bottom Layer "Bottom Layer-No Net 2" (solid, remove dead copper, pour order 122): 40,1680 40,40 2620,40 2620,1680
NetC7_1 on Bottom Layer "Bottom Layer-No Net" (solid, remove dead copper, pour order 120): 1280,1360 1280,1280 1000,1280 920,1200 820,1200 820,1250 930,1360

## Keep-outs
Keep-Out Layer:
  text ".Layer_Name" at 577,-858.49 h60

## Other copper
Top Layer:
  text ".Layer_Name" at 577,-858.49 h60
Bottom Layer:
  text ".Layer_Name" at 577,-858.49 h60

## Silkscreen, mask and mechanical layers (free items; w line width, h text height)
Top Overlay:
  lines w10: 370,290 370,1420 2570,1420 2570,290 370,290
  text "'.PRJ_Title'" at 1553,1592 h50
  text "56x29mm" at 370,1470 h70
  text "Rev. '.PCB_Rev'" at 1553,1462 h50
  text ".Layer_Name" at 577,-858.49 h60
Bottom Overlay:
  text ".Layer_Name" at 577,-858.49 h60
Top Paste:
  text ".Layer_Name" at 577,-858.49 h60
Bottom Paste:
  text ".Layer_Name" at 577,-858.49 h60
Top Solder:
  text ".Layer_Name" at 577,-858.49 h60
  text ".Layer_Name" at 577,-858.49 h60
Bottom Solder:
  text ".Layer_Name" at 577,-858.49 h60
Drill Guide:
  text ".Layer_Name" at 577,-858.49 h60
M1 Board Outline:
  the board outline again, w10
  text ".Layer_Name" at 577,-858.49 h60
M2 Board Dimensions:
  rectangle: 125,-400 500,-275
  rectangle: 0,-275 125,-150
  lines w7: 0,-275 1000,-275 ; 125,-400 125,-150 ; 250,-400 250,-150 ; 500,-400 500,-150 ; 750,-400 750,-150 ; 0,-400 0,-150 1000,-150 1000,-400 0,-400
  text ".Layer_Name" at 577,-858.49 h60
M3 3D STEP Top:
  text ".Layer_Name" at 577,-858.49 h60
M4 3D STEP Bottom:
  text ".Layer_Name" at 577,-858.49 h60
M5 Assembly Top:
  lines w10: -292,-930.17 6308,-930.17 ; -292,-726.83 6310,-726.83 ; -292,-523.5 -292,-1133.5 3713,-1133.5 6310,-1133.5 6310,-523.5 -291.5,-523.5 -291.5,-1133.5 1284,-1133.5 ; 2173,-1133.5 2173,-523.5 ; 3440,-726.83 3440,-523.5 ; 4280,-726.83 4280,-523.5 ; 4902,-1140 4902,-937.17
  text "COMPONENTS MARKED 'DNP' SHOULD NOT BE POPULATED." at 1153.5,-318.5 h60
  text "ASSEMBLY VARIANT:" at 1153,-434 h60
  text ".VariantName" at 2189,-434 h60
  text "PCB VIEWED FROM TOP SIDE" at -228.5,-655.67 h60
  text "BOARD #:" at 2248,-655.67 h60
  text ".PRJ_Number" at 2793.5,-655.67 h60
  text "REV:" at 3638,-655.67 h60
  text ".PCB_Rev" at 3929.5,-655.67 h60
  text "SVN REV:" at 4476,-655.67 h60
  text ".VersionControl_RevNumber" at 4982,-655.67 h60
  text "TID #:" at 2248,-859 h60
  text ".TID" at 2793.5,-859 h60
  text "PLOT NAME =" at -228.5,-1064.34 h60
  text ".plot_File_Name" at 577,-1064.34 h60
  text "GENERATED    :" at 2250,-1064.34 h60
  text ".Print_Date" at 3119.5,-1064.34 h60
  text ".Print_Time" at 3848.5,-1064.34 h60
  text "TEXAS INSTRUMENTS" at 5113,-1064.34 h60
M6 Assembly Bottom:
  lines w10: -292.5,-727.33 6309.5,-727.33 ; -290.5,-930.67 6309.5,-930.67 ; 1115.5,-1140.5 1115.5,-937.67 ; 1737.5,-727.33 1737.5,-524 ; 2577.5,-727.33 2577.5,-524 ; 3844.5,-1134 3844.5,-524 ; 4733.5,-1134 6309,-1134 6309,-524 -292.5,-524 -292.5,-1134 2304.5,-1134 6309.5,-1134 6309.5,-524
  text "COMPONENTS MARKED 'DNP' SHOULD NOT BE POPULATED." at 6102,-318 h60
  text ".VariantName" at 5058,-434 h60
  text "ASSEMBLY VARIANT:" at 6097,-434 h60
  text ".VersionControl_RevNumber" at 1035.5,-656.17 h60
  text "SVN REV:" at 1541.5,-656.17 h60
  text ".PCB_Rev" at 2088,-656.17 h60
  text "REV:" at 2379.5,-656.17 h60
  text ".PRJ_Number" at 3224,-656.17 h60
  text "BOARD #:" at 3769.5,-656.17 h60
  text "PCB VIEWED FROM BOTTOM SIDE" at 6246,-656.17 h60
  text ".TID" at 3224,-859.5 h60
  text "TID #:" at 3769.5,-859.5 h60
  text "TEXAS INSTRUMENTS" at 904.5,-1064.84 h60
  text ".Print_Time" at 2169,-1064.84 h60
  text ".Print_Date" at 2898,-1064.84 h60
  text "GENERATED    :" at 3767.5,-1064.84 h60
  text ".plot_File_Name" at 5440.5,-1064.84 h60
  text "PLOT NAME =" at 6246,-1064.84 h60
M9 Title Sheet:
  drawing of 57 lines, arcs and shapes, not listed
  text "1" at 739.84,8036.5 h70
  text "2" at 3235.5,8036.5 h70
  text "3" at 5724.84,8036.5 h70
  text "4" at 8231.51,8036.5 h70
  text "5" at 10730.5,8036.5 h70
  text "6" at 13235.5,8036.5 h70
  text "A" at -416.5,6893.5 h70
  text "A" at 14383.5,6893.5 h70
  text "B" at -416.5,4513.5 h70
  text "B" at 14383.5,4513.5 h70
  text "C" at -416.5,2138.5 h70
  text "C" at 14383.5,2138.5 h70
  text "PROJECT TITLE:" at 11343.5,277.5 h45
  text ".PRJ_Title" at 11393.5,144.17 h70
  text "DESIGNED FOR:" at 11343.5,-23.5 h45
  text ".PRJ_Customer" at 11393.5,-163.5 h70
  text "D" at -416.5,-231.5 h70
  text "D" at 14383.5,-231.5 h70
  text "FILE NAME:" at 11343.5,-323.5 h45
  text ".PCB_File_Name_No_Path" at 11393.5,-443.5 h70
  text "Texas Instruments (TI) and/or its licensors do not warrant the accuracy or completeness of this specification" at 6374,-605.34 h45
  text "ENGINEER:" at 11343.5,-613.5 h45
  text "LAYOUT BY:" at 12848.5,-613.5 h45
  text "or any information contained therein. TI and/or its licensors do not warrant that this design will meet" at 6329.01,-718 h45
  text ".PRJ_Engineer" at 11393.5,-768.49 h70
  text ".PCB_Layout" at 12899,-768.49 h70
  text "the specifications, will be suitable for your application or fit for any particular purpose, or will operate in" at 6329.01,-830.67 h45
  text ".Layer_Name" at 577,-858.49 h60
  text "ALTIUM DESIGNER VERSION:" at 12848.5,-923.5 h45
  text "an implementation. TI and/or its licensors do not warrant that the design is production worthy. You should" at 6329.01,-943.33 h45
  text "completely validate and test your design implementation to confirm the system functionality for your application." at 6374,-1056 h45
  text ".print_Scale" at 11393.5,-1056.83 h70
  text ".Application_BuildNumber" at 12899,-1056.83 h70
  text "1" at 739.84,-1263.5 h70
  text "2" at 3235.5,-1263.5 h70
  text "3" at 5724.84,-1263.5 h70
  text "4" at 8231.51,-1263.5 h70
  text "5" at 10730.5,-1263.5 h70
  text "6" at 13235.5,-1263.5 h70
M10 Fab Notes:
  drawing of 173 lines, arcs and shapes, not listed
  text "DESIGN INFORMATION" at 12378.02,6201 h60
  text "MIN. TRACK WIDTH:" at 11733.46,6021 h60
  text "9" at 12829.7,6021 h60
  text "MIL" at 12984.46,6021 h60
  text "MIN. CLEARANCE:" at 11733.46,5889 h60
  text "0.2" at 12769.7,5889 h60
  text "mm" at 12984.46,5889 h60
  text "27.599" at 12615.72,5758.1 h60
  text "MIN. VIA PAD SIZE:" at 11733.46,5757 h60
  text "MIL" at 12984.46,5757 h60
  text "0.05mm (2MIL)" at 12428.46,5615.29 h60
  text "MINIMUM ANNULAR RING" at 11404.23,5611 h60
  text "EXTERNAL" at 13136.46,5611 h60
  text "PER" at 11604.23,5493 h60
  text "IPC-D-275 CLASS 2 LEVEL C" at 11824.23,5493 h60
  text "MIL, HOLES" at 13312.46,5380.71 h60
  text "+/-" at 12920,5380 h60
  text "+/-" at 13774,5380 h60
  text "REGISTRATION TOLERANCES:" at 11404.23,5375 h60
  text "METAL" at 12604,5375 h60
  text "5" at 13180.2,5375 h60
  text "3" at 14013.2,5375 h60
  text "MIL" at 14129.46,5375 h60
  text "+/-" at 13774,5262 h60
  text "HOLE SIZE TOLERANCE (UNLESS OTHERWISE SPECIFIED):" at 11404.23,5257 h60
  text "3" at 14013.2,5257 h60
  text "MIL" at 14129.46,5257 h60
  text "MATERIAL:" at 11329.46,5047.54 h60
  text "FR-4 High Tg" at 12315.9,4907.21 h60
  text "FR-408" at 11750.46,4898.64 h60
  text "OTHER" at 13238.46,4898.64 h60
  text "X" at 12161,4895 h60
  text "40 MIL (1.0mm) +/-10%" at 12070.56,4735.92 h60
  text "THICKNESS:" at 11404.23,4731.64 h60
  text "X" at 11942.4,4731.64 h60
  text "OTHER" at 13355.46,4731.64 h60
  text "TOLERANCE:" at 11404.23,4573.64 h60
  text "X" at 12243.53,4573.64 h60
  text "ANSI IPC-6012 TYPE 3 CLASS 2" at 12430.48,4573.64 h60
  text "OTHER +/-" at 12430.46,4417.64 h60
  text "BOW & TWIST:" at 11404.23,4260.64 h60
  text "X" at 12243.53,4260.64 h60
  text "ANSI IPC-6012 TYPE 3 CLASS 2" at 12430.48,4260.64 h60
  text "OTHER +/-" at 12430.46,4102.13 h60
  text "DRILLING:" at 11329.46,3963.64 h60
  text "REFERENCE:" at 11404.23,3846.64 h60
  text "X" at 12052.46,3846.64 h60
  text "AS SHOWN" at 12239.46,3846.64 h60
  text "X" at 12953.46,3846.64 h60
  text "NC_DRILL FILES" at 13090.46,3846.64 h60
  text "PTH COPPER THICKNESS:" at 11404.23,3688.64 h60
  text "X" at 12534.46,3688.64 h60
  text "20-30 um" at 12671.46,3688.64 h60
  text "OTHER" at 13388.46,3688.64 h60
  text "BOARD FINISH:" at 11329.46,3529.64 h60
  text "SILKSCREEN:" at 11484.68,3411.64 h60
  text "X" at 12433.46,3411.64 h60
  text "TOP" at 12559.46,3411.64 h60
  text "BOTTOM" at 13070.46,3411.64 h60
  text "SILKSCREEN COLOR:" at 11484.68,3244.64 h60
  text "X" at 12432.42,3244.64 h60
  text "WHITE" at 12559.46,3244.64 h60
  text "OTHER" at 13070.46,3244.64 h60
  text "X" at 12563.42,3085.44 h60
  text "GREEN" at 12690.46,3085.44 h60
  text "OTHER" at 13308.46,3085.44 h60
  text "SOLDER RESIST COLOR:" at 11484.68,3074.64 h60
  text "X" at 12563.42,2915.44 h60
  text "MATTE" at 12690.46,2915.44 h60
  text "SEMI-GLOSS" at 13308,2914.8 h60
  text "IMMERSION GOLD (ENIG)" at 12390.46,2726.92 h60
  text "ENEPIG" at 13728,2723.64 h60
  text "SURFACE FINISH:" at 11329.46,2722.64 h60
  text "X" at 12203.51,2722.64 h60
  text "IMM. TIN/SILVER OR EQUIV" at 11659,2565.64 h60
  text "OTHER" at 13090.46,2565.64 h60
  text "ARRAY/PANEL:" at 11329.46,2386.64 h60
  text "CUT AND TRIM PER M1 BOARD OUTLINE" at 12390.46,2382.35 h60
  text "N.C. ROUTE" at 12390.46,2230.64 h60
  text "X" at 13069.46,2230.64 h60
  text "V. SCORE" at 13256.46,2230.64 h60
  text "CERTIFICATION:" at 11329.46,2093.64 h60
  text "MATERIALS AND WORKMANSHIP FOR ALL PCBS" at 12054.46,2093.64 h60
  text "TO MEET OR EXCEED THE REQUIREMENTS OF:" at 12054.46,1995.64 h60
  text "X" at 11680.96,1859.13 h60
  text "ANSI IPC-A-600F CLASS ->" at 11819.96,1859.13 h60
  text "X" at 13459.02,1859.13 h60
  text "2" at 13577.96,1859.14 h60
  text "1" at 13262.96,1857.64 h60
  text "3" at 13931.96,1857.64 h60
  text "X" at 12495.02,1699.64 h60
  text "RoHS" at 12631.96,1699.64 h60
  text "OTHER" at 13276.36,1699.64 h60
  text "PER ORDER" at 13673.42,1699.64 h60
  text "ALL BOARDS MUST MEET OR EXCEED UL94-V0 REQUIREMENTS." at 11357,1534 h60
  text "PCB MUST BEAR THE UL94V-0 UL REGISTERED MATERIAL ID NUMBER" at 11357,1414 h60
  text "ADDITIONAL REQUIREMENTS:" at 11329.46,1240.64 h60
  text "MICROSECTION:" at 11404.23,1125.64 h60
  text "YES" at 12309.96,1125.64 h60
  text "REQUIRED" at 13171.46,969.49 h60
  text "BARE BOARD ELEC. TEST:" at 11404.23,966.64 h60
  text "NONE" at 12709.96,966.64 h60
  text "X" at 13044.46,966.64 h60
  text "PER ORDER" at 13763.46,966.64 h60
  text ".Layer_Name" at 577,-858.49 h60
M11 Gerber Information:
  lines w10: -292,-930.17 6308,-930.17 ; -292,-726.83 6310,-726.83 ; -292,-523.5 -292,-1133.5 3713,-1133.5 6310,-1133.5 6310,-523.5 -291.5,-523.5 -291.5,-1133.5 1284,-1133.5 ; 2173,-1133.5 2173,-523.5 ; 3440,-726.83 3440,-523.5 ; 4280,-726.83 4280,-523.5 ; 4902,-1140 4902,-937.17
  text "ALL ARTWORK VIEWED FROM TOP SIDE" at -228.5,-655.67 h60
  text "BOARD #:" at 2248,-655.67 h60
  text ".PRJ_Number" at 2793.5,-655.67 h60
  text "REV:" at 3638,-655.67 h60
  text ".PCB_Rev" at 3929.5,-655.67 h60
  text "SVN REV:" at 4476,-655.67 h60
  text ".VersionControl_RevNumber" at 4982,-655.67 h60
  text "LAYER NAME =" at -228.5,-858.49 h60
  text "TID #:" at 2248,-859 h60
  text ".TID" at 2793.5,-859 h60
  text "PLOT NAME =" at -228.5,-1064.34 h60
  text ".plot_File_Name" at 577,-1064.34 h60
  text "GENERATED    :" at 2250,-1064.34 h60
  text ".Print_Date" at 3119.5,-1064.34 h60
  text ".Print_Time" at 3848.5,-1064.34 h60
  text "TEXAS INSTRUMENTS" at 5113,-1064.34 h60
M12 Stackup:
  drawing of 191 lines, arcs and shapes, not listed
  text "Layer" at 9797.84,7830 h60
  text "Name" at 10207.76,7830 h60
  text "Material" at 11137.5,7830 h60
  text "Thickness" at 11997.27,7830 h60
  text "Constant" at 12647.1,7830 h60
  text "Board Layer Stack" at 13216.96,7830 h60
  text "1" at 9797.84,7710 h60
  text "Top Overlay" at 10207.76,7710 h60
  text "2" at 9797.84,7590 h60
  text "Top Solder" at 10207.76,7590 h60
  text "Solder Resist" at 11137.5,7590 h60
  text "0.40mil" at 11997.27,7590 h60
  text "3.5" at 12647.1,7590 h60
  text "3" at 9797.84,7470 h60
  text "Top Layer" at 10207.76,7470 h60
  text "Copper" at 11137.5,7470 h60
  text "1.40mil" at 11997.27,7470 h60
  text "4" at 9797.84,7350 h60
  text "Dielectric1" at 10207.76,7350 h60
  text "FR-4" at 11137.5,7350 h60
  text "37.20mil" at 11997.27,7350 h60
  text "4.8" at 12647.1,7350 h60
  text "5" at 9797.84,7230 h60
  text "Bottom Layer" at 10207.76,7230 h60
  text "Copper" at 11137.5,7230 h60
  text "1.40mil" at 11997.27,7230 h60
  text "6" at 9797.84,7110 h60
  text "Bottom Solder" at 10207.76,7110 h60
  text "Solder Resist" at 11137.5,7110 h60
  text "0.40mil" at 11997.27,7110 h60
  text "3.5" at 12647.1,7110 h60
  text "7" at 9797.84,6990 h60
  text "Bottom Overlay" at 10207.76,6990 h60
  text ".Layer_Name" at 577,-858.49 h60
M13 Component Bodies Top:
  text ".Layer_Name" at 577,-858.49 h60
M14 Component Bodies Bottom:
  text ".Layer_Name" at 577,-858.49 h60
M15 Courtyards Top:
  text ".Layer_Name" at 577,-858.49 h60
M16 Courtyards Bottom:
  text ".Layer_Name" at 577,-858.49 h60
Drill Drawing:
  circle w10: c2883.72,1405.96 r27.63
  lines w10: 2856.09,1060.63 2911.34,1060.63 2883.72,1005.38 2856.09,1060.63 ; 2856.09,1129.7 2911.34,1129.7 2911.34,1184.95 2856.09,1184.95 2856.09,1129.7 ; 2856.09,1267.83 2869.9,1267.83 2883.72,1254.02 2897.53,1267.83 2911.34,1267.83 2897.53,1281.64 2911.34,1295.46 2897.53,1295.46 2883.72,1309.27 2869.9,1295.46 2856.09,1295.46 2869.9,1281.64 2856.09,1267.83 ; 2856.09,1502.66 2883.72,1516.47 2911.34,1502.66 2897.53,1530.28 2911.34,1557.91 2883.72,1544.1 2856.09,1557.91 2869.9,1530.28 2856.09,1502.66
  lines w12: 2806,968.08 6037.49,968.08 ; 2806,1589.68 6037.49,1589.68 ; 3143.86,843.76 3143.86,1714 ; 3475.86,843.76 3475.86,1714 ; 4112.43,843.76 4112.43,1714 ; 4371.57,843.76 4371.57,1714 ; 4746.72,843.76 4746.72,1714 ; 5471.05,843.76 5471.05,1714 ; 2806,843.76 6037.49,843.76 6037.49,1714 2806,1714 2806,843.76
  text "Symbol" at 2880.59,1626.98 h72
  text "Quantity" at 3181.16,1626.98 h72
  text "Finished Hole Size" at 3513.16,1626.98 h72
  text "Plated" at 4149.72,1626.98 h72
  text "Hole Type" at 4408.86,1626.98 h72
  text "Drill Layer Pair" at 4784.02,1626.98 h72
  text "Hole Tolerance" at 5508.35,1626.98 h72
  text "28" at 3181.16,1502.66 h60
  text "7.87mil (0.200mm)" at 3513.16,1502.66 h60
  text "PTH" at 4149.72,1502.66 h60
  text "Round" at 4408.86,1502.66 h60
  text "Top Layer - Bottom Layer" at 4784.02,1502.66 h60
  text "62" at 3181.16,1378.34 h60
  text "11.81mil (0.300mm)" at 3513.16,1378.34 h60
  text "PTH" at 4149.72,1378.34 h60
  text "Round" at 4408.86,1378.34 h60
  text "Top Layer - Bottom Layer" at 4784.02,1378.34 h60
  text "2" at 3181.16,1254.02 h60
  text "29.53mil (0.750mm)" at 3513.16,1254.02 h60
  text "PTH" at 4149.72,1254.02 h60
  text "Round" at 4408.86,1254.02 h60
  text "Top Layer - Bottom Layer" at 4784.02,1254.02 h60
  text "15" at 3181.16,1129.7 h60
  text "45.28mil (1.150mm)" at 3513.16,1129.7 h60
  text "PTH" at 4149.72,1129.7 h60
  text "Round" at 4408.86,1129.7 h60
  text "Top Layer - Bottom Layer" at 4784.02,1129.7 h60
  text "2" at 3181.16,1005.38 h60
  text "50.00mil (1.270mm)" at 3513.16,1005.38 h60
  text "PTH" at 4149.72,1005.38 h60
  text "Round" at 4408.86,1005.38 h60
  text "Top Layer - Bottom Layer" at 4784.02,1005.38 h60
  text "109 Total" at 3181.16,881.06 h60
  text ".Layer_Name" at 577,-858.49 h60
Mechanical 17:
  text ".Layer_Name" at 577,-858.49 h60
Mechanical 18:
  text ".Layer_Name" at 577,-858.49 h60
Mechanical 19:
  text ".Layer_Name" at 577,-858.49 h60

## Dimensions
0,0 to 2660,0 on M2 Board Dimensions
0,0 to 0,1720 on M2 Board Dimensions
0,-400 to 1000,-400 on M2 Board Dimensions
